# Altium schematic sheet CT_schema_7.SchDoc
size 391 x 301 mm
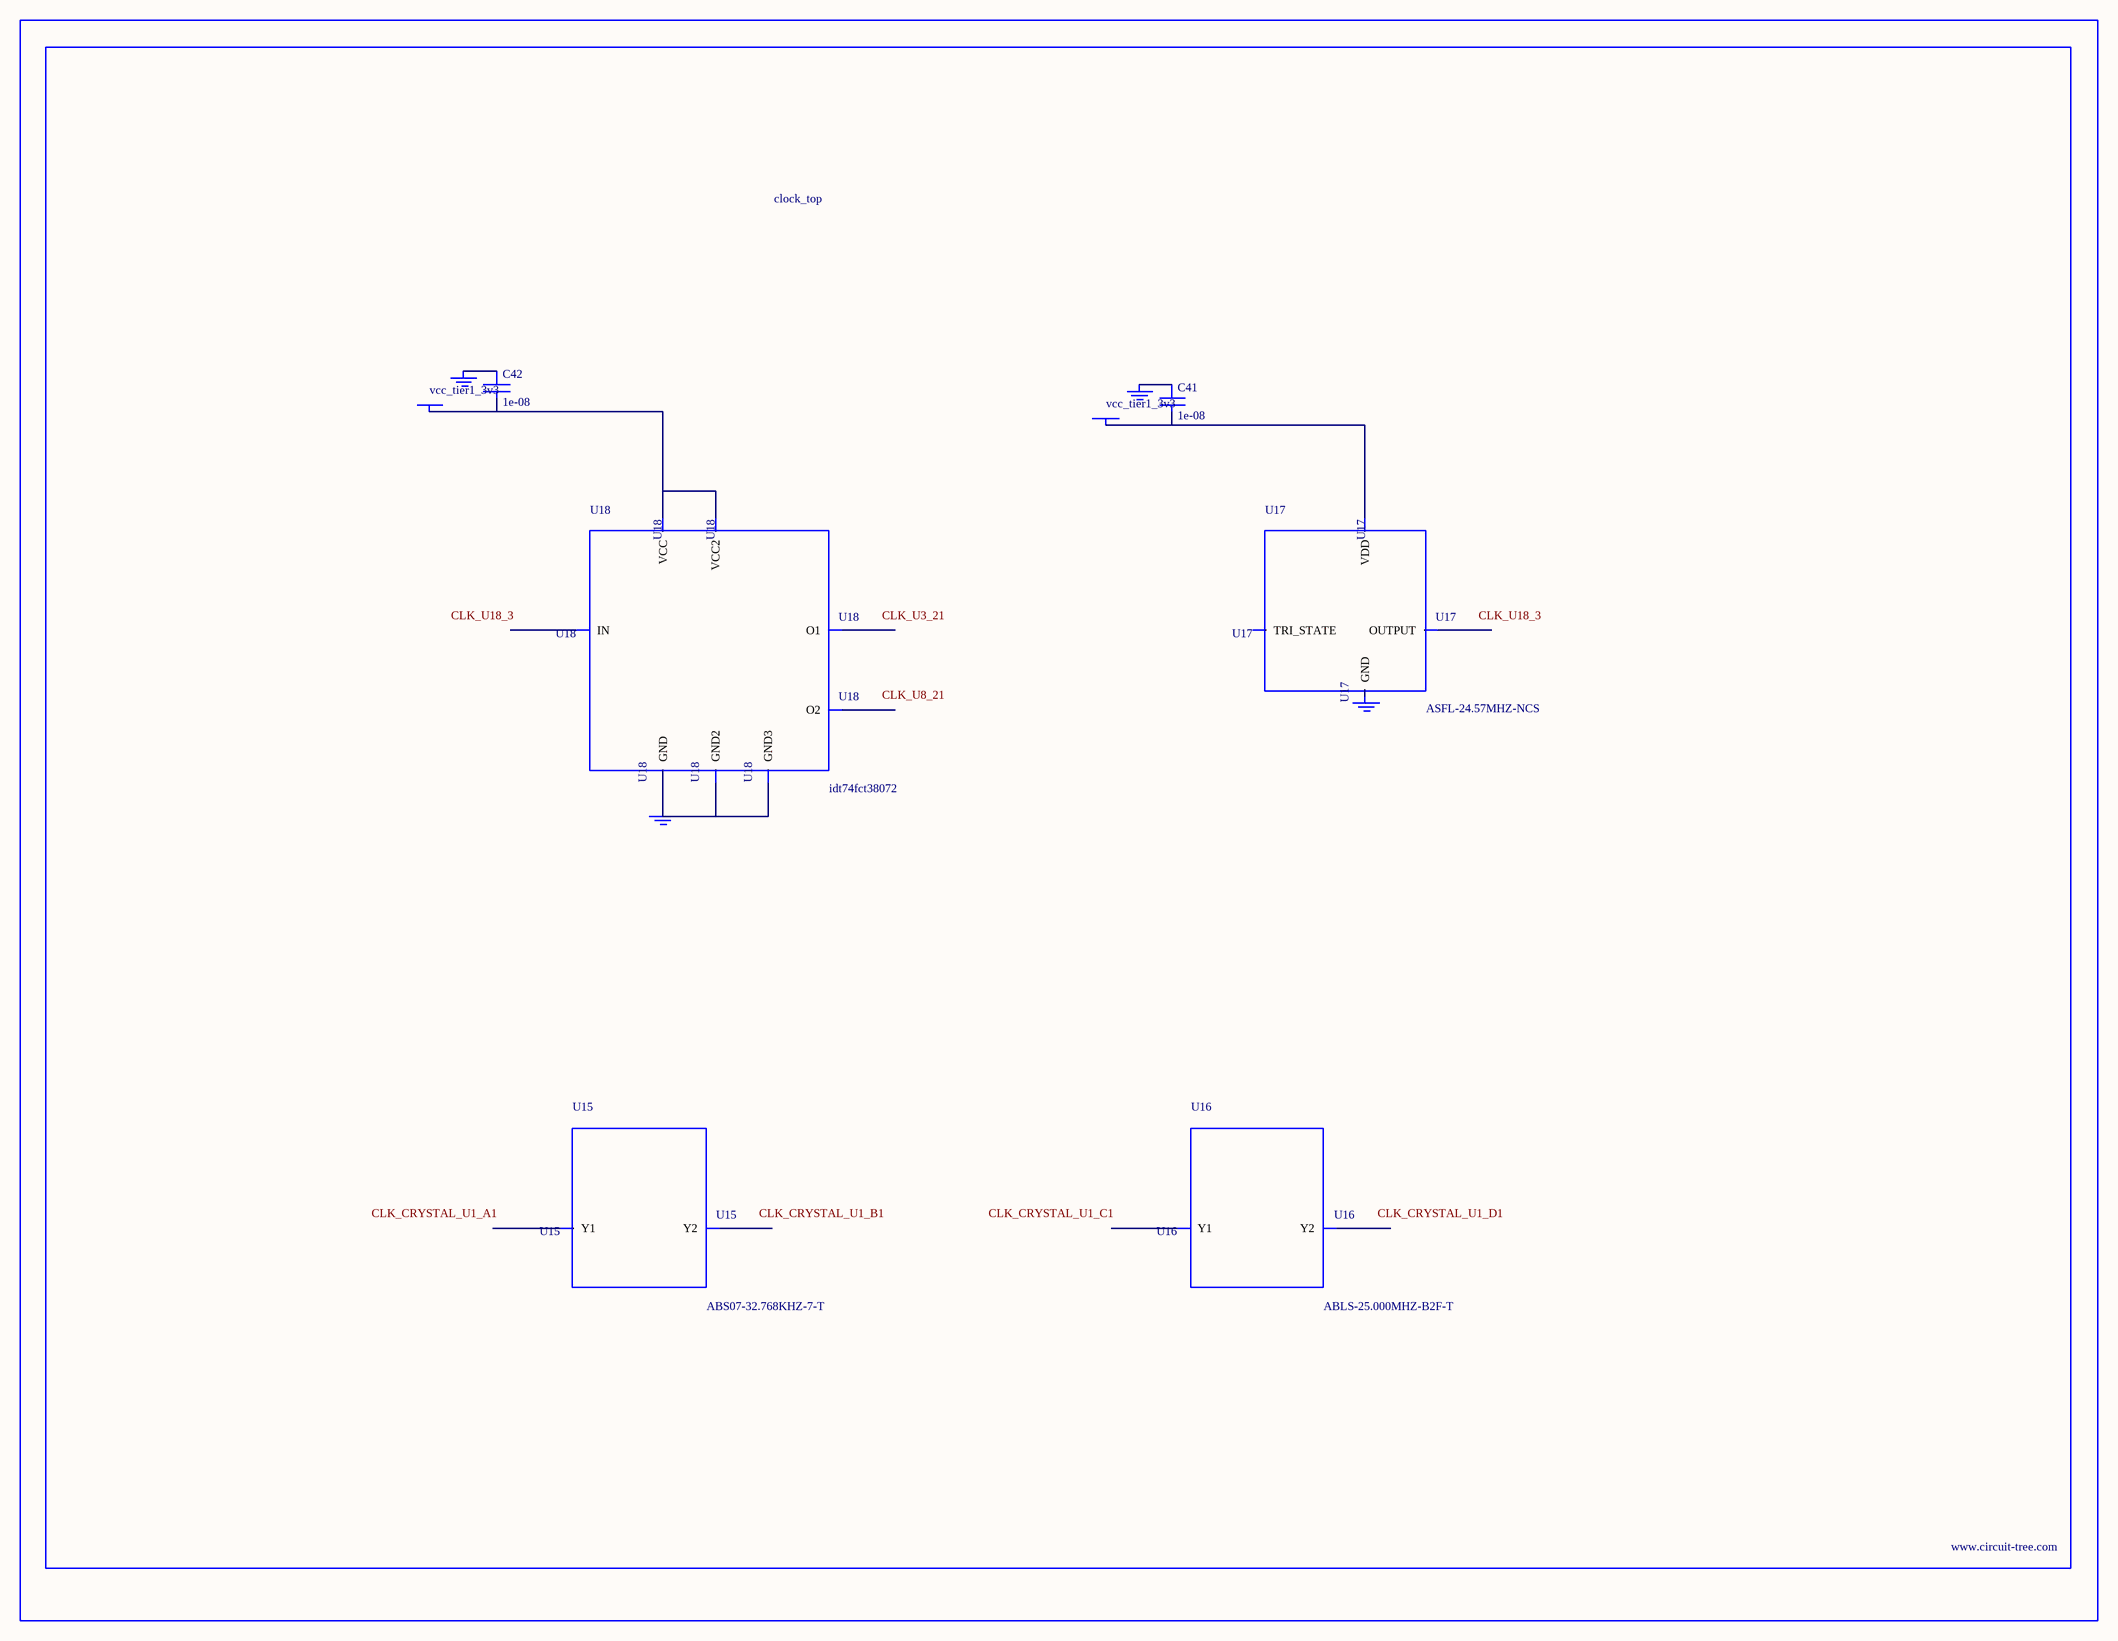
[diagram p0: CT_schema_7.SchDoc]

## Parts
BORDER6  (no value)
C41  1e-08  [C0402]
C42  1e-08  [C0402]
GND_INSTANCE_6_0  (no value)
GND_INSTANCE_6_1  (no value)
GND_INSTANCE_6_2  (no value)
GND_INSTANCE_6_3  (no value)
POWER_INSTANCE_6_0  vcc_tier1_3v3
POWER_INSTANCE_6_1  vcc_tier1_3v3
U15  ABS07-32.768KHZ-7-T  [ABS07-32.768KHZ-7-T]
U16  ABLS-25.000MHZ-B2F-T  [ABLS-25.000MHZ-B2F-T]
U17  ASFL-24.57MHZ-NCS  [ASFL1]
U18  idt74fct38072  [IDT74FCT38072]

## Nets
NetC41_1: C41.1 GND_INSTANCE_6_0.0(GND)
NetC41_2: C41.2 POWER_INSTANCE_6_0.0(PWR) U17.4(VDD)
NetC42_1: C42.1 GND_INSTANCE_6_2.0(GND)
NetC42_2: C42.2 POWER_INSTANCE_6_1.0(PWR) U18.1(VCC) U18.2(VCC2)
NetGND_INSTANCE_6_3_0: GND_INSTANCE_6_3.0(GND) U18.4(GND) U18.5(GND2) U18.8(GND3)

Not connected (* = marked no-connect by the designer): GND_INSTANCE_6_1 0(GND); U15 1(Y1) 2(Y2); U16 1(Y1) 2(Y2); U17 1(TRI_STATE) 2(GND) 3(OUTPUT); U18 3(IN) 6(O2) 7(O1)

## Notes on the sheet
- Labels drawn without touching a wire or pin: CLK_CRYSTAL_U1_A1, CLK_CRYSTAL_U1_B1, CLK_CRYSTAL_U1_C1, CLK_CRYSTAL_U1_D1, CLK_U3_21, CLK_U8_21, CLK_U18_3

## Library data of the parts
BORDER6 = BORDER_PAGE6
C41 C42 = C0402C103K3RAC
GND_INSTANCE_6_0-GND_INSTANCE_6_3 = GND
POWER_INSTANCE_6_0 POWER_INSTANCE_6_1 = PWR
